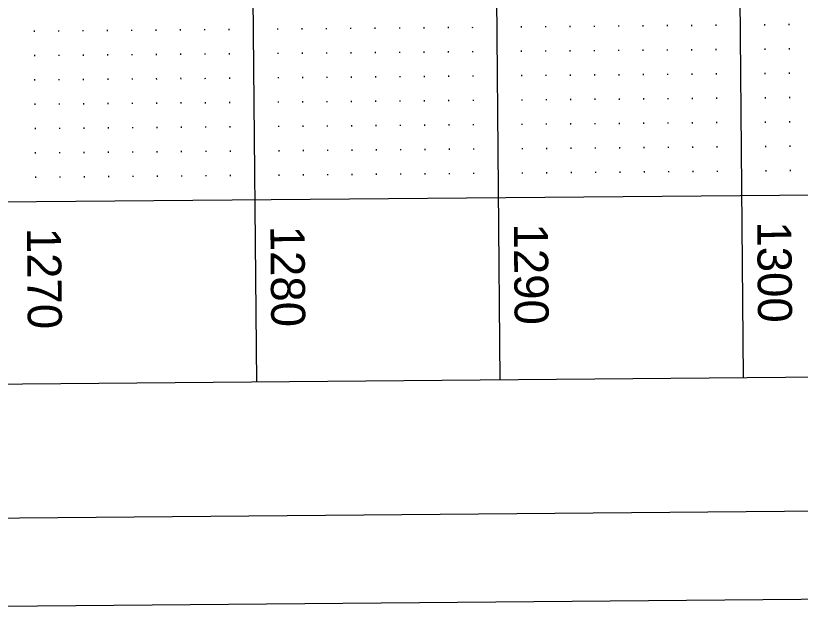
# Model space of a CAD drawing. Extents: x 2149873 to 2152007, y 140538 to 142349.
# Drawn here: x 2150190.1 to 2150351.2, y 140538.2 to 140662.2 of the extents above; entities that cross this region are included whole.
import ezdxf

# ---------------------------------------------------------------- set-up
doc = ezdxf.new("R2010")
doc.units = 0
for name, color, linetype in [('SHT_Plan_Profile_Sheet_Elev_Txt', 7, 'Continuous'), ('SHT_Plot_Shape_Full', 7, 'Continuous'), ('SHT_Plot_Shape_Half', 7, 'Continuous'), ('SHT_Profile_Grid_Major', 7, 'Continuous'), ('SHT_Profile_Grid_Minor', 7, 'Continuous'), ('SHT_Sheet_Border', 7, 'Continuous')]:
    doc.layers.add(name, color=color, linetype=linetype)

msp = doc.modelspace()

# ---------------------------------------------------------------- linework, layer by layer
at = {"layer": 'SHT_Plot_Shape_Full'}
msp.add_lwpolyline([(2151072.86, 142348.62), (2151088.62, 140548.69), (2149888.66, 140538.18), (2149872.91, 142338.11)], close=True, dxfattribs=at)
at = {"layer": 'SHT_Plot_Shape_Half'}
msp.add_lwpolyline([(2151032.33, 142266.38), (2151047.21, 140566.45), (2149947.25, 140556.82), (2149932.37, 142256.76)], close=True, dxfattribs=at)
at = {"layer": 'SHT_Profile_Grid_Major'}
for p, q in [((2150225.72, 142161.82), (2150239.5, 140586.88)), ((2150275.71, 142162.26), (2150289.5, 140587.32)), ((2150325.71, 142162.69), (2150339.5, 140587.76))]:
    msp.add_line(p, q, dxfattribs=at)
at = {"layer": 'SHT_Profile_Grid_Minor'}
for p, q in [((2150253.87, 140659.63), (2150253.87, 140659.38)), ((2150258.87, 140659.68), (2150258.87, 140659.43)), ((2150263.87, 140659.72), (2150263.87, 140659.47)), ((2150268.87, 140659.76), (2150268.87, 140659.51)), ((2150273.87, 140659.81), (2150273.87, 140659.56)), ((2150278.87, 140659.85), (2150278.87, 140659.6)), ((2150283.86, 140659.9), (2150283.87, 140659.65)), ((2150293.86, 140659.98), (2150293.87, 140659.73)), ((2150298.86, 140660.03), (2150298.87, 140659.78)), ((2150303.86, 140660.07), (2150303.87, 140659.82)), ((2150308.86, 140660.11), (2150308.87, 140659.86)), ((2150313.86, 140660.16), (2150313.87, 140659.91)), ((2150318.86, 140660.2), (2150318.87, 140659.95)), ((2150323.86, 140660.25), (2150323.87, 140660)), ((2150328.86, 140660.29), (2150328.87, 140660.04)), ((2150333.86, 140660.33), (2150333.87, 140660.08)), ((2150343.86, 140660.42), (2150343.86, 140660.17)), ((2150348.86, 140660.46), (2150348.86, 140660.21)), ((2150193.87, 140659.11), (2150193.87, 140658.86)), ((2150198.87, 140659.15), (2150198.87, 140658.9)), ((2150203.87, 140659.2), (2150203.87, 140658.95)), ((2150208.87, 140659.24), (2150208.87, 140658.99)), ((2150213.87, 140659.28), (2150213.87, 140659.03)), ((2150218.87, 140659.33), (2150218.87, 140659.08)), ((2150223.87, 140659.37), (2150223.87, 140659.12)), ((2150228.87, 140659.41), (2150228.87, 140659.16)), ((2150233.87, 140659.46), (2150233.87, 140659.21)), ((2150243.87, 140659.55), (2150243.87, 140659.3)), ((2150248.87, 140659.59), (2150248.87, 140659.34)), ((2150268.91, 140654.76), (2150268.91, 140654.51)), ((2150273.91, 140654.81), (2150273.91, 140654.56)), ((2150278.91, 140654.85), (2150278.91, 140654.6)), ((2150283.91, 140654.9), (2150283.91, 140654.65)), ((2150293.91, 140654.98), (2150293.91, 140654.73)), ((2150298.91, 140655.03), (2150298.91, 140654.78)), ((2150303.91, 140655.07), (2150303.91, 140654.82)), ((2150308.91, 140655.11), (2150308.91, 140654.86)), ((2150313.91, 140655.16), (2150313.91, 140654.91)), ((2150318.91, 140655.2), (2150318.91, 140654.95)), ((2150323.91, 140655.25), (2150323.91, 140655)), ((2150328.91, 140655.29), (2150328.91, 140655.04)), ((2150333.91, 140655.33), (2150333.91, 140655.08)), ((2150343.91, 140655.42), (2150343.91, 140655.17)), ((2150348.91, 140655.46), (2150348.91, 140655.21)), ((2150193.91, 140654.11), (2150193.91, 140653.86)), ((2150198.91, 140654.15), (2150198.91, 140653.9)), ((2150203.91, 140654.2), (2150203.91, 140653.95)), ((2150208.91, 140654.24), (2150208.91, 140653.99)), ((2150213.91, 140654.28), (2150213.91, 140654.03)), ((2150218.91, 140654.33), (2150218.91, 140654.08)), ((2150223.91, 140654.37), (2150223.91, 140654.12)), ((2150228.91, 140654.41), (2150228.91, 140654.16)), ((2150233.91, 140654.46), (2150233.91, 140654.21)), ((2150243.91, 140654.55), (2150243.91, 140654.3)), ((2150248.91, 140654.59), (2150248.91, 140654.34)), ((2150253.91, 140654.63), (2150253.91, 140654.38)), ((2150258.91, 140654.68), (2150258.91, 140654.43)), ((2150263.91, 140654.72), (2150263.91, 140654.47)), ((2150293.95, 140649.98), (2150293.95, 140649.73)), ((2150298.95, 140650.03), (2150298.95, 140649.78)), ((2150303.95, 140650.07), (2150303.95, 140649.82)), ((2150308.95, 140650.12), (2150308.95, 140649.87)), ((2150313.95, 140650.16), (2150313.95, 140649.91)), ((2150318.95, 140650.2), (2150318.95, 140649.95)), ((2150323.95, 140650.25), (2150323.95, 140650)), ((2150328.95, 140650.29), (2150328.95, 140650.04)), ((2150333.95, 140650.33), (2150333.95, 140650.08)), ((2150343.95, 140650.42), (2150343.95, 140650.17)), ((2150348.95, 140650.47), (2150348.95, 140650.22)), ((2150193.96, 140649.11), (2150193.96, 140648.86)), ((2150198.96, 140649.15), (2150198.96, 140648.9)), ((2150203.96, 140649.2), (2150203.96, 140648.95)), ((2150208.96, 140649.24), (2150208.96, 140648.99)), ((2150213.96, 140649.28), (2150213.96, 140649.03)), ((2150218.95, 140649.33), (2150218.96, 140649.08)), ((2150223.95, 140649.37), (2150223.96, 140649.12)), ((2150228.95, 140649.41), (2150228.96, 140649.16)), ((2150233.95, 140649.46), (2150233.96, 140649.21)), ((2150243.95, 140649.55), (2150243.96, 140649.3)), ((2150248.95, 140649.59), (2150248.96, 140649.34)), ((2150253.95, 140649.63), (2150253.96, 140649.38)), ((2150258.95, 140649.68), (2150258.96, 140649.43)), ((2150263.95, 140649.72), (2150263.96, 140649.47)), ((2150268.95, 140649.76), (2150268.96, 140649.51)), ((2150273.95, 140649.81), (2150273.95, 140649.56)), ((2150278.95, 140649.85), (2150278.95, 140649.6)), ((2150283.95, 140649.9), (2150283.95, 140649.65)), ((2150309, 140645.12), (2150309, 140644.87)), ((2150314, 140645.16), (2150314, 140644.91)), ((2150318.99, 140645.2), (2150319, 140644.95)), ((2150323.99, 140645.25), (2150324, 140645)), ((2150328.99, 140645.29), (2150329, 140645.04)), ((2150333.99, 140645.33), (2150334, 140645.08)), ((2150343.99, 140645.42), (2150344, 140645.17)), ((2150348.99, 140645.47), (2150349, 140645.22)), ((2150194, 140644.11), (2150194, 140643.86)), ((2150199, 140644.15), (2150199, 140643.9)), ((2150204, 140644.2), (2150204, 140643.95)), ((2150209, 140644.24), (2150209, 140643.99)), ((2150214, 140644.28), (2150214, 140644.03)), ((2150219, 140644.33), (2150219, 140644.08)), ((2150224, 140644.37), (2150224, 140644.12)), ((2150229, 140644.41), (2150229, 140644.16)), ((2150234, 140644.46), (2150234, 140644.21)), ((2150244, 140644.55), (2150244, 140644.3)), ((2150249, 140644.59), (2150249, 140644.34)), ((2150254, 140644.63), (2150254, 140644.38)), ((2150259, 140644.68), (2150259, 140644.43)), ((2150264, 140644.72), (2150264, 140644.47)), ((2150269, 140644.77), (2150269, 140644.52)), ((2150274, 140644.81), (2150274, 140644.56)), ((2150279, 140644.85), (2150279, 140644.6)), ((2150284, 140644.9), (2150284, 140644.65)), ((2150294, 140644.98), (2150294, 140644.73)), ((2150299, 140645.03), (2150299, 140644.78)), ((2150304, 140645.07), (2150304, 140644.82)), ((2150329.04, 140640.29), (2150329.04, 140640.04)), ((2150334.04, 140640.33), (2150334.04, 140640.08)), ((2150344.04, 140640.42), (2150344.04, 140640.17)), ((2150349.04, 140640.47), (2150349.04, 140640.22)), ((2150194.04, 140639.11), (2150194.05, 140638.86)), ((2150199.04, 140639.15), (2150199.05, 140638.9)), ((2150204.04, 140639.2), (2150204.05, 140638.95)), ((2150209.04, 140639.24), (2150209.04, 140638.99)), ((2150214.04, 140639.28), (2150214.04, 140639.03)), ((2150219.04, 140639.33), (2150219.04, 140639.08)), ((2150224.04, 140639.37), (2150224.04, 140639.12)), ((2150229.04, 140639.42), (2150229.04, 140639.17)), ((2150234.04, 140639.46), (2150234.04, 140639.21)), ((2150244.04, 140639.55), (2150244.04, 140639.3)), ((2150249.04, 140639.59), (2150249.04, 140639.34)), ((2150254.04, 140639.63), (2150254.04, 140639.38)), ((2150259.04, 140639.68), (2150259.04, 140639.43)), ((2150264.04, 140639.72), (2150264.04, 140639.47)), ((2150269.04, 140639.77), (2150269.04, 140639.52)), ((2150274.04, 140639.81), (2150274.04, 140639.56)), ((2150279.04, 140639.85), (2150279.04, 140639.6)), ((2150284.04, 140639.9), (2150284.04, 140639.65)), ((2150294.04, 140639.98), (2150294.04, 140639.73)), ((2150299.04, 140640.03), (2150299.04, 140639.78)), ((2150304.04, 140640.07), (2150304.04, 140639.82)), ((2150309.04, 140640.12), (2150309.04, 140639.87)), ((2150314.04, 140640.16), (2150314.04, 140639.91)), ((2150319.04, 140640.2), (2150319.04, 140639.95)), ((2150324.04, 140640.25), (2150324.04, 140640)), ((2150344.08, 140635.42), (2150344.08, 140635.17)), ((2150349.08, 140635.47), (2150349.08, 140635.22)), ((2150194.09, 140634.11), (2150194.09, 140633.86)), ((2150199.09, 140634.15), (2150199.09, 140633.9)), ((2150204.09, 140634.2), (2150204.09, 140633.95)), ((2150209.09, 140634.24), (2150209.09, 140633.99)), ((2150214.09, 140634.28), (2150214.09, 140634.03)), ((2150219.09, 140634.33), (2150219.09, 140634.08)), ((2150224.09, 140634.37), (2150224.09, 140634.12)), ((2150229.09, 140634.42), (2150229.09, 140634.17)), ((2150234.09, 140634.46), (2150234.09, 140634.21)), ((2150244.09, 140634.55), (2150244.09, 140634.3)), ((2150249.09, 140634.59), (2150249.09, 140634.34)), ((2150254.08, 140634.63), (2150254.09, 140634.38)), ((2150259.08, 140634.68), (2150259.09, 140634.43)), ((2150264.08, 140634.72), (2150264.09, 140634.47)), ((2150269.08, 140634.77), (2150269.09, 140634.52)), ((2150274.08, 140634.81), (2150274.09, 140634.56)), ((2150279.08, 140634.85), (2150279.09, 140634.6)), ((2150284.08, 140634.9), (2150284.09, 140634.65)), ((2150294.08, 140634.98), (2150294.09, 140634.73)), ((2150299.08, 140635.03), (2150299.09, 140634.78)), ((2150304.08, 140635.07), (2150304.09, 140634.82)), ((2150309.08, 140635.12), (2150309.08, 140634.87)), ((2150314.08, 140635.16), (2150314.08, 140634.91)), ((2150319.08, 140635.2), (2150319.08, 140634.95)), ((2150324.08, 140635.25), (2150324.08, 140635)), ((2150329.08, 140635.29), (2150329.08, 140635.04)), ((2150334.08, 140635.33), (2150334.08, 140635.08)), ((2150194.13, 140629.11), (2150194.13, 140628.86)), ((2150199.13, 140629.15), (2150199.13, 140628.9)), ((2150204.13, 140629.2), (2150204.13, 140628.95)), ((2150209.13, 140629.24), (2150209.13, 140628.99)), ((2150214.13, 140629.28), (2150214.13, 140629.03)), ((2150219.13, 140629.33), (2150219.13, 140629.08)), ((2150224.13, 140629.37), (2150224.13, 140629.12)), ((2150229.13, 140629.42), (2150229.13, 140629.17)), ((2150234.13, 140629.46), (2150234.13, 140629.21)), ((2150244.13, 140629.55), (2150244.13, 140629.3)), ((2150249.13, 140629.59), (2150249.13, 140629.34)), ((2150254.13, 140629.63), (2150254.13, 140629.38)), ((2150259.13, 140629.68), (2150259.13, 140629.43)), ((2150264.13, 140629.72), (2150264.13, 140629.47)), ((2150269.13, 140629.77), (2150269.13, 140629.52)), ((2150274.13, 140629.81), (2150274.13, 140629.56)), ((2150279.13, 140629.85), (2150279.13, 140629.6)), ((2150284.13, 140629.9), (2150284.13, 140629.65)), ((2150294.13, 140629.98), (2150294.13, 140629.73)), ((2150299.13, 140630.03), (2150299.13, 140629.78)), ((2150304.13, 140630.07), (2150304.13, 140629.82)), ((2150309.13, 140630.12), (2150309.13, 140629.87)), ((2150314.13, 140630.16), (2150314.13, 140629.91)), ((2150319.13, 140630.2), (2150319.13, 140629.95)), ((2150324.13, 140630.25), (2150324.13, 140630)), ((2150329.13, 140630.29), (2150329.13, 140630.04)), ((2150334.13, 140630.33), (2150334.13, 140630.08)), ((2150344.13, 140630.42), (2150344.13, 140630.17)), ((2150349.12, 140630.47), (2150349.13, 140630.22))]:
    msp.add_line(p, q, dxfattribs=at)
at = {"layer": 'SHT_Sheet_Border'}
msp.add_line((2150014.18, 140622.41), (2150489.16, 140626.57), dxfattribs=at)
msp.add_lwpolyline([(2151008.19, 142168.67), (2151021.97, 140593.73), (2149972.01, 140584.54), (2149958.23, 142159.48)], close=True, dxfattribs=at)

# ---------------------------------------------------------------- texts
at = {"layer": 'SHT_Plan_Profile_Sheet_Elev_Txt'}
for s, p in [('1270', (2150192.38, 140618.57)), ('1280', (2150242.38, 140619.01)), ('1290', (2150292.38, 140619.45)), ('1300', (2150342.37, 140619.89))]:
    msp.add_text(s, height=7, rotation=270.5015, dxfattribs=at).set_placement(p)

doc.saveas('drawing.dxf')
